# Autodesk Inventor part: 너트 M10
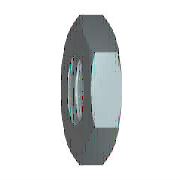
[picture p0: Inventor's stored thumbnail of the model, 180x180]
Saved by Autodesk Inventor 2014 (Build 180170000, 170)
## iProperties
IsCustomPart: 1
Created: 2012-02
Part Number: 너트 M10
Material: 스테인리스강
Description: 미터법 정밀 피치 스레드가 있는 6각 가는 너트(모따기됨)
Document SubType Name: Modeling
Standard: ISO 8675
Designer: mduedu
Standard Revision: Second edition 1999-08-15
Standards Organization: ISO
Language: ko-KR
Size Designation: M10 x 1
Categories: <MemberInstance><Categories><Category DisplayName="조임쇠" InternalName="e4da775c-781d-43d5-af7c-5136215cf5a6" Mnemonic="FSTN"><Category DisplayName="너트" InternalN
Density: 8.08 g/cm^3
Appearance: 기본값
Author: mduedu
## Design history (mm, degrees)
sketch "스케치1"
  geometry: L1 (-9.238, 0)-(-4.619, 8); L2 (-4.619, 8)-(4.619, 8); L3 (4.619, 8)-(9.238, 0); L4 (9.238, 0)-(4.619, -8); L5 (4.619, -8)-(-4.619, -8); L6 (-4.619, -8)-(-9.238, 0); 2 further points
  constraints: 12 end point, 1 coincident, 1 horizontal, 11 other
  dimensions: "d0" = 18.47521 distance of L3.end L1.start (= 1.1547 x SW)
extrude "본체" new body sketch "스케치1" distance "d1" = 5 (= KOH); taper "d2" = 0 deg
sketch "스케치2"
  geometry: L1 (0, 4.619)-(0, 9.238) reference; L2 (0, 9.238)-(5, 9.238) reference; L3 (5, 4.619)-(5, 9.238) reference; L4 (-1, 0)-(6, 0) reference; L5 (1.11, 9.238)-(0, 7.315); L6 (3.89, 9.238)-(5, 7.315)
  constraints: 4 end point, 4 point on line
  dimensions: "d3" = 30 deg angle of L1 L5 (= ANG1); "d4" = 30 deg angle of L3 L6 (= ANG2); "d5" = 14.63 diameter of L5.end L4 (= SW0); "d6" = 14.63 diameter of L6.end L4 (= SW01)
revolve "모따기1" sketch "스케치2" stored, may be unused: angle "d7" = 90 deg
sketch "스케치3"
  geometry: 4 further points
  constraints: 1 coincident, 1 other
hole "스레드" sketch "스케치3" at (0, 0) diameter "d25" = 8.91747; stored, may be unused: countersink angle "d29" = 82 deg, drill point angle "d31" = 118 deg; dims "d26" = 6, "d27" = 4, "d28" = 2, "d30" = 8
workaxis "Work Axis1"
workplane "Work Plane1"
body "Solid1"
chamfer "모따기2" distance "d8" = 0.54127 (= -0.5 x GD1 + 0.5 x NND); stored, may be unused: angle "d9" = 30 deg, second distance "d40" = 0.54127 (= -0.5 x GD1 + 0.5 x NND)
chamfer "모따기3" distance "d10" = 0.54127 (= -0.5 x GD1 + 0.5 x NND); stored, may be unused: angle "d11" = 30 deg, second distance "d41" = 0.54127 (= -0.5 x GD1 + 0.5 x NND)
other parameters: "ANG1" = 30 deg [user parameter; used in 1 equation term], "ANG2" = 30 deg [user parameter; used in 1 equation term], "KOH" = 5 [user parameter; used in 1 equation term], "SW" = 16 [user parameter; used in 1 equation term], "SW0" = 14.63 [user parameter; used in 2 equation terms], "SW01" = 14.63 (= SW0) [user parameter; used in 1 equation term], "GD1" = 8.91747 (computed from THREADDIA, PTC, TOA) [user parameter; used in 4 equation terms], "d13" = 0, "d14" = 0, "d39" = 0, "d42" = 0, "GUL" = 0.54127 (= 0.541266 x PTC) [user parameter], "TOA" = 30 deg [user parameter; used in 1 equation term], "PTC" = 1 [user parameter; used in 4 equation terms], "E0" = 17.77 [user parameter], "GAL" = 0.54127 (= 0.541266 x PTC) [user parameter]
